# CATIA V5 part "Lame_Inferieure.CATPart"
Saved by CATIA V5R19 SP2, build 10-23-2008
Part number: Lame_Inferieure
Bounding box of the stored display mesh (mm): x 0 to 2, y -41.7 to 7.367, z -5.544 to 5.451
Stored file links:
  G:\EU_thinkMotion\CFAO_2010\MMS_groupe3\MMS_groupe3\A reprendre\lletoffe\lletoffe_Thinkmotion_CFAO\Modèle Catia\Lame_Inferieure.CATPart
  E:\CFAO\Last Catia\Lame inferieure.CATPart
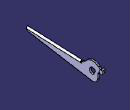
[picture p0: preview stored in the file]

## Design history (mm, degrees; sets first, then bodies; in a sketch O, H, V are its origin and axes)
Parameters
  Epaisseur = 1 mm
  Longueur_lame_inf = 35 mm
Set1
  Point1: (0, 0, 0)
  Point2: (1, 0, 0)
  Line1: type PtPt, FirstPoint Point1, SecondPoint Point2, Start 10, End 10
  Plane1: type Offset, RefPlane yz-plane, Offset 1 {= Epaisseur}
  Plane2: type Offset, RefPlane Plane1, Offset 1 {= Epaisseur}
  Sketch1 on yz-plane, origin (0, 0, 0), H (0, 1, 0), V (0, 0, 1)
    arc A1 centre (0, 0) radius 2 from (1.9487, 0.4499) to (0.7815, -1.841) ccw
    point P1 (0.7815, -1.841)
    arc A2 centre (-39.7012, 3.0585) radius 2 from (-41.6996, 3.1377) to (-40.0299, 1.0857) ccw
    arc A3 centre (-6.638, 4) radius 2.25 from (-6.7271, 1.7518) to (-4.7108, 2.8387) ccw
    arc A4 centre (0.25, -2.5848) radius 3 from (-0.2431, -5.544) to (3.25, -2.5848) ccw
    line L1 (3.25, 0) -> (3.25, -2.5848)
    arc A5 centre (4.25, 0) radius 1 from (4.0048, 0.9695) to (3.25, 0) ccw
    line L2 (-40.0299, 1.0857) -> (-0.2431, -5.544)
    construction line L3 through (0, -0.0584) direction (0, 1)
    construction line L4 through (0, 0) direction (1, 0)
    point P2 (4.25, 0)
    line L5 (3.796, 3.98) -> (4.8814, 2.9447)
    arc A6 centre (0, 0) radius 5.5 from (3.796, 3.98) to (-4.7108, 2.8387) ccw
    line L6 (4.0048, 0.9695) -> (6.4285, 1.5825)
    point P3 (6.4285, 1.5825)
    point P4 (6.4285, 1.5825)
    point P5 (6.9854, 3.7018)
    point P6 (6.9854, 3.7018)
    line L7 (6.2618, 4.392) -> (6.9854, 3.7018)
    arc A7 centre (6.1215, 2.796) radius 1.2517 from (6.4285, 1.5825) to (6.9854, 3.7018) ccw
    point P7 (6.9854, 3.7018)
    point P8 (4.8814, 2.9447)
    point P9 (6.2618, 4.392)
    point P10 (6.2618, 4.392)
    point P11 (4.8814, 2.9447)
    line L8 (4.8814, 2.9447) -> (6.2618, 4.392)
    point P13 (-6.7271, 1.7518)
    point P14 (-39.7012, 3.0585)
    point P15 (-6.638, 4)
    point P16 (0, 0)
    point P25 (0.7815, -1.841)
    construction line L9 (-6.7271, 1.7518) -> (-41.6996, 3.1377)
    line L10 (-41.6996, 3.1377) -> (-7.7263, 1.7914)
    line L11 (-7.7263, 1.7914) -> (-7.7659, 0.7921)
    point P33 (-7.7659, 0.7921)
    line L12 (-7.7659, 0.7921) -> (-6.7667, 0.7525)
    line L13 (-6.7667, 0.7525) -> (-6.7271, 1.7518)
    point P35 (-6.7271, 1.7518)
    line L14 (0.9482, -0.4831) -> (1.9487, 0.4499)
    construction line L15 (-0.718, -0.6696) -> (0.7183, 0.6698)
    reference projected point E1 (0, 0) from Line1
    reference projected point E2 (0, 0) from Line1
    reference projected point E3 (0, 0) from Line1
    line L16 (0.9482, -0.4831) -> (0.7815, -1.841)
    axis line L17 (-0.2591, -2.1103) -> (-0.4021, -3.2748)
    reference projected point E4 (0, 0) from Line1
    radius A1 = 2
    radius A2 = 2
    radius A3 = 2.25
    radius A4 = 3
    distance L3 L1 = 3.25
    radius A5 = 1
    radius A6 = 5.5
    length L6 = 2.5
    distance L6 P8 = 1.7
    length L8 = 2
    length L5 = 1.5
    distance L8 P5 = 1
    distance P15 L4 = 4
    length L9 = 35 {= Longueur_lame_inf}
    distance L13 L11 = 1
    distance L15 L14 = 1
    distance P33 L10 = 1
    angle L16 L3 = 7
    distance L17 L16 = 1
    angle L17 L14 = 40
    coincidence: P1 A1, P2 L4, P4 P3, P6 P5, P5 P7, P10 P9, P11 P8, P35 P13, P14 L10, P1 P25, L15 E1, L3 E2, L4 E3, P16 L4, P16 L3, L17 E4
    tangency: L1 A4, L1 A5, L2 A4, L2 A2, A6 L5, A6 A3, L6 A5, A7 L7, L6 A7, L9 A3, L10 A3
    fix: L2
    perpendicularity: L5 L8, L12 L11, L13 L12, L11 L10, L3 L4, L8 L7
    concentricity: A6 A1
    vertical: L3 V
  Sketch2 on Plane1, origin (1, 0, 0), H (0, 1, 0), V (0, 0, 1)
    point P1 (6.2618, 4.392)
    line L1 (6.2618, 4.392) -> (6.9854, 3.7018)
    arc A1 centre (6.1215, 2.796) radius 1.2517 from (6.9854, 3.7018) to (6.4285, 1.5825) cw
    reference projected line E1 (7.2355, 3.4633) -> (6.5119, 4.1535) from Sketch1.L7
    reference projected arc E2 centre (6.1215, 2.796) radius 1.2517 from (6.2243, 1.5485) to (6.833, 3.8259) ccw from Sketch1.A7
    line L2 (4.8814, 2.9447) -> (5.8982, 1.4484)
    point P5 (4.8814, 2.9447)
    point P6 (5.8982, 1.4484)
    reference projected line E3 (4.0048, 0.9695) -> (6.4285, 1.5825) from Sketch1.L6
    line L3 (6.2618, 4.392) -> (4.8814, 2.9447)
    point P7 (6.2618, 4.392)
    point P8 (4.8814, 2.9447)
    reference projected point E4 (4.8814, 2.9447) from vertex [element of Sketch1 | element of Sketch1]
    reference projected line E5 (6.2618, 4.392) -> (4.8814, 2.9447) from Sketch1.L8
    reference projected line E6 (4.0048, 0.9695) -> (6.4285, 1.5825) from Sketch1.L6
    angle L2 E6 = 70
    tangency: A1 L1
    coincidence: L1 E1, A1 E2, P6 E3, P7 P1, P8 E4, L3 E5, P5 P8
Body1 (main body)
  Pad1: profile Sketch1, direction (1, 0, 0), up to Plane1
  Pad2: profile Sketch2, direction (1, 0, 0), up to Plane2
  Chamfer1: length 1, angle 45, on edge [end face of Pad1 | face of Pad1 from Sketch1.L10]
